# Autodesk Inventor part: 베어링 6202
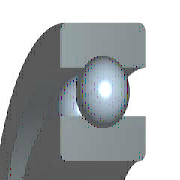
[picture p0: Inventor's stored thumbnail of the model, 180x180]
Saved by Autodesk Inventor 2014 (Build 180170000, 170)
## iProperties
Created: 2015-12
Part Number: 베어링 6202
Material: 강철, 연강
Description: 깊은 그루브 볼 베어링
Document SubType Name: Modeling
Standard: KS B 2023
Designer: mdu
Standards Organization: KS
Language: ko-KR
Size Designation: 6202 - 15 x 35 x 11
Categories: <MemberInstance><Categories><Category DisplayName="샤프트 부품" InternalName="7f7aeb1f-a693-4053-b835-cee3144e0d98" Mnemonic="SHFT"><Category DisplayName="베어링" Inter
Density: 7.86 g/cm^3
Mass: 42.4004 g
Surface Area: 51.5584 cm^2
Volume: 5.39445 cm^3
Appearance: 노란색
Company: 한국ATC센터
IsCustomPart: 1
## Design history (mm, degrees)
sketch "스케치" dims "d0" = 5.2 (= -0.26 x WD + 0.26 x BD)
  geometry: L1 (2.9, 12.5)-(8.1, 12.5); L2 (5.5, 12.5)-(5.5, 9.9); L3 (5.5, 12.5)-(5.5, 15.1); L4 (3.568, 10.76)-(0, 10.76); L5 (0, 7.5)-(11, 7.5); L6 (3.568, 14.24)-(0, 14.24); L7 (0, 17.5)-(11, 17.5); L8 (11, 7.5)-(11, 10.76); L9 (7.432, 10.76)-(11, 10.76); L10 (7.432, 14.24)-(11, 14.24); L11 (11, 17.5)-(11, 14.24); L12 (-1.4, 0)-(8.4, 0) reference; L13 (0, -0.3)-(0, 5.3) reference
  constraints: 22 end point, 4 point on line, 2 collinear, 2 perpendicular, 2 symmetric about line, 1 midpoint, 1 parallel, 14 other
  dimensions: "d9" = 15 diameter of L5 L12 (= WD); "d11" = 35 diameter of L7 L12 (= BD); "d12" = 11 distance between parallel lines of L8 L13 (= KB); "d13" = 21.52 diameter of L9 L12 (= 0.326 x BD + 0.674 x WD)
revolve "본체" stored, may be unused: angle "d6" = 90 deg
revolve "볼" stored, may be unused: angle "d7" = 90 deg
pattern_circular "IDS_ARRAYBALL[SIMPL:T]" dims angle "d3" = 360 deg
body "Solid1"
fillet "모깎기1" dims "d1" = 0.6 (= KRS)
other parameters: "WD" = 15 [user parameter; used in 5 equation terms], "BD" = 35 [user parameter; used in 5 equation terms], "KB" = 11 [user parameter; used in 1 equation term], "KRS" = 0.6 [user parameter; used in 1 equation term], "d4" = 0, "d5" = 0, "d8" = 0, "d14" = 0, "d15" = 0, "BBA" = 0 [user parameter], "BC0" = 3750000 [user parameter], "BC" = 7800000 [user parameter], "BR" = 17.5 (= 0.5 x BD) [user parameter], "WR" = 7.5 (= 0.5 x WD) [user parameter]
